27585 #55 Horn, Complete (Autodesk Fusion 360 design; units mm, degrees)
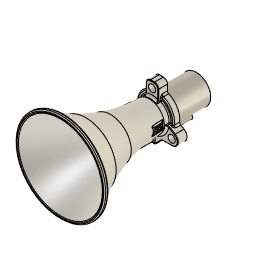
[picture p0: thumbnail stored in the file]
parameter "Bolt_Hole_Tolerance" = 1.5875 (= "( 1 / 16 ) * 1 in")
parameter "Dowel_Hole_Tolerance" = 0.0248 (= "( 1 / 1024 ) * 1 in")
parameter "d277" = 55
parameter "d278" = 1.7223
parameter "d279" = 63
parameter "d280" = 1.5875 (= "( 1 / 16 ) * 1 in")
parameter "d281" = 0.5095
parameter "d282" = 0.5095 (= "d281")
parameter "d283" = 0.5095 (= "d281")
parameter "d284" = 0.5095 (= "d281")
parameter "d285" = 1.5875 (= "( 1 / 16 ) * 1 in")
parameter "d287" = 0.4159
parameter "d288" = 9.219
parameter "d289" = 0.6307
parameter "d290" = 0.4047
parameter "d291" = 0.4047 (= "d290")
parameter "d292" = 0.4571
parameter "d293" = 0.4571 (= "d292")
parameter "d294" = 1.5875 (= "( 1 / 16 ) * 1 in")
parameter "d295" = 1.5875 (= "( 1 / 16 ) * 1 in")
parameter "d296" = 1.5875 (= "( 1 / 16 ) * 1 in")
parameter "d297" = 1.5875 (= "d296")
parameter "d298" = 0.3969 (= "( 1 / 64 ) * 1 in")
parameter "d299" = 0.3969 (= "( 1 / 64 ) * 1 in")
parameter "d300" = 0.3969 (= "( 1 / 64 ) * 1 in")
parameter "d301" = 0.3969 (= "d300")
parameter "d302" = 0.4047 (= "d290")
parameter "d303" = 0.4047 (= "d302")
parameter "d304" = 0.7839 (= "d305")
parameter "d305" = 0.7839
parameter "d306" = 0.7839 (= "d305")
parameter "d307" = 0.3969 (= "( 1 / 64 ) * 1 in")
parameter "d308" = 0.3969 (= "d307")
parameter "d309" = 1.5875 (= "( 1 / 16 ) * 1 in")
parameter "d310" = 0.7937 (= "( 1 / 32 ) * 1 in")
parameter "d311" = 0.3969 (= "( 1 / 64 ) * 1 in")
parameter "d312" = 0.3969 (= "( 1 / 64 ) * 1 in")
parameter "d313" = 1.5875 (= "( 1 / 16 ) * 1 in")
parameter "d314" = 0.3969 (= "( 1 / 64 ) * 1 in")
parameter "d317" = 0.3969 (= "( 1 / 64 ) * 1 in")
parameter "d318" = 109
parameter "d319" = 0.3969 (= "( 1 / 64 ) * 1 in")
parameter "d320" = 1.5875 (= "( 1 / 16 ) * 1 in")
parameter "d321" = 0.3969 (= "( 1 / 64 ) * 1 in")
parameter "d322" = 0.3969 (= "( 1 / 64 ) * 1 in")
parameter "d323" = 109
parameter "d324" = 0.7937 (= "( 1 / 32 ) * 1 in")
parameter "d326" = 0.3969 (= "( 1 / 64 ) * 1 in")
parameter "d327" = 0.3969 (= "( 1 / 64 ) * 1 in")
parameter "d328" = 1.5875 (= "( 1 / 16 ) * 1 in")
parameter "d329" = 1.7223 (= "d278")
parameter "d330" = 0.3969 (= "( 1 / 64 ) * 1 in")
parameter "d331" = 0.3969 (= "d330")
parameter "d332" = 1.3496
parameter "d333" = 0.3969 (= "d330")
parameter "d334" = 1.5875 (= "( 1 / 16 ) * 1 in")
parameter "d335" = 0.3969 (= "d330")
parameter "d342" = 1.5875 (= "( 1 / 16 ) * 1 in")
parameter "d336" = 0.3969 (= "( 1 / 64 ) * 1 in")
parameter "d337" = 0.3969 (= "d336")
parameter "d338" = 0.3969 (= "d337")
parameter "d340" = 0.3969 (= "( 1 / 64 ) * 1 in")
canvas "Canvas1"
sketch "Main Profile" plane through (0, 0, 0) normal (1, 0, 0) x axis (0, 1, 0)
  line L1 (0, -22.225) -> (0, 22.225)
  line L2 (-53.975, 22.225) -> (0, 22.225)
  line L3 (-53.975, 44.45) -> (-53.975, 22.225)
  line L4 (-210.3438, 0) -> (0, 0)
  line L5 (-68.2625, 44.45) -> (-53.975, 44.45)
  line L6 (-53.975, -22.225) -> (0, -22.225)
  line L7 (-53.975, 22.225) -> (-53.975, -22.225)
  line L8 (-53.975, -38.1) -> (-53.975, -22.225)
  line L9 (-68.2625, -38.1) -> (-53.975, -38.1)
  line L10 (-68.2625, 44.45) -> (-68.2625, -38.1)
  line L11 (-67.3186, 16.4106) -> (0, 11.1125)
  line L12 (-63.5, 28.575) -> (-53.975, 28.575)
  line L13 (-63.5, 19.2949) -> (-63.5, 28.575)
  line L14 (-67.0695, 19.5758) -> (-63.5, 19.2949)
  line L15 (-210.3438, -69.0563) -> (-210.3437, 69.0562)
  line L16 (-68.2625, 19.6697) -> (-68.2625, 44.45)
  line L17 (9.1828, 34.925) -> (-68.2625, 34.925)
  line L18 (-34.1313, 22.225) -> (-34.1313, -22.225)
  line L19 (-68.2625, -18.1085) -> (-68.2625, -38.1)
  line L20 (-205.5813, 69.0562) -> (-210.3437, 69.0562)
  line L21 (-205.5812, 65.9557) -> (-205.5813, 69.0562)
  line L22 (-141.1555, -34.925) -> (-68.2625, -34.925)
  line L23 (-67.3186, 0) -> (-67.3186, 16.4106)
  line L24 (-67.3186, -16.4106) -> (0, -11.1125)
  line L25 (-205.5812, -65.9557) -> (-205.5812, -69.0563)
  line L26 (-205.5812, -69.0563) -> (-210.3437, -69.0563)
  line L27 (-67.0695, -19.5758) -> (-63.5, -19.2949)
  line L28 (-63.5, 23.0187) -> (-68.2625, 23.0187)
  line L29 (-72.4156, 23.0187) -> (-68.2625, 23.0187)
  arc A1 centre (-43.4043, 320.271) radius 304.8 clockwise from (-67.3186, 16.4106) to (-210.3438, 65.2529)
  arc A2 centre (-43.4043, 320.271) radius 301.625 clockwise from (-67.0695, 19.5758) to (-210.3438, 69.0562)
  arc A3 centre (-43.4043, -320.271) radius 304.8 clockwise from (-210.3437, -65.2529) to (-67.3186, -16.4106)
  arc A4 centre (-43.4043, -320.271) radius 301.625 clockwise from (-210.3437, -69.0563) to (-67.0695, -19.5758)
  arc A5 centre (-72.4156, 226.2188) radius 203.2 clockwise from (-72.4156, 23.0187) to (-132.3099, 32.0464)
  point P4 (0, 0)
  point P1 (0, 0)
  point P7 (0, 0)
  point P13 (0, 11.1125)
  point P15 (-53.975, 28.575)
  point P21 (-210.3438, 0)
  point P8 (-210.3438, 0)
  point P22 (-68.2625, 19.6697)
  point P23 (-68.2625, 34.925)
  point P25 (-34.1313, -22.225)
  point P26 (-34.1313, 22.225)
  point P27 (-68.2625, -18.1085)
  point P30 (-68.2625, -34.925)
  point P32 (-68.2625, 23.0187)
  point P33 (-210.3438, 65.2529)
  point P37 (-67.3186, 0)
  point P35 (-210.3438, 69.0562)
  point P29 (-205.5812, 65.9557)
  point P19 (-210.3437, 69.0562)
  point P38 (0, -11.1125)
  point P14 (-67.3186, 16.4106)
  point P39 (-67.3186, -16.4106)
  point P17 (-63.5, 19.2949)
  point P48 (-63.5, -19.2949)
  point P18 (-67.0695, 19.5758)
  point P44 (-67.0695, -19.5758)
  point P47 (-210.3437, -69.0563)
  point P28 (-205.5813, 69.0562)
  point P45 (-205.5812, -69.0563)
  point P46 (-205.5812, -65.9557)
  point P41 (-210.3437, -65.2529)
  point P43 (-210.3437, -69.0563)
  point P31 (-141.1555, -34.925)
  point P49 (-63.5, 23.0187)
  point P51 (-132.3099, 32.0464)
  point P2 (0, 22.225)
  point P5 (-53.975, 22.225)
  point P3 (0, -22.225)
  point P6 (-53.975, 44.45)
  point P9 (-68.2625, 44.45)
  point P16 (-63.5, 28.575)
  point P20 (-210.3438, -69.0563)
  point P12 (-68.2625, -38.1)
  vertical L1
  coincident L1 P4
  coincident P1 P4
  midpoint P1 L1
  perpendicular L1 L2
  perpendicular L2 L3
  coincident P1 P7
  perpendicular L1 L4
  perpendicular L3 L5
  perpendicular L1 L6
  vertical L7
  perpendicular L6 L8
  perpendicular L8 L9
  vertical L10
  coincident L1 P13
  coincident L3 P15
  perpendicular L3 L12
  perpendicular L12 L13
  parallel L11 L14
  vertical L15
  midpoint L15 P21
  coincident P8 P21
  coincident L14 P22
  coincident L10 P22
  coincident L10 P23
  perpendicular L16 L17
  coincident L6 P25
  coincident L2 P26
  perpendicular L2 L18
  coincident L10 P27
  perpendicular L9 L19
  perpendicular L15 L20
  vertical L21
  coincident L10 P30
  perpendicular L19 L22
  coincident L10 P32
  coincident L15 P33
  tangent L11 A1
  tangent L14 A2
  concentric A1 A2
  coincident L4 P37
  perpendicular L4 L23
  coincident L15 P35
  coincident P29 A2
  coincident P19 P35
  symmetric L4 P13 P38
  symmetric L4 P14 P39
  symmetric L4 P17 P48
  symmetric L4 P18 P44
  symmetric L4 P19 P47
  symmetric L4 P28 P45
  symmetric L4 P29 P46
  symmetric L4 P33 P41
  symmetric L4 A1 A3
  symmetric L4 P35 P43
  symmetric L4 A2 A4
  coincident P31 A4
  coincident L13 P49
  perpendicular L13 L28
  perpendicular L10 L29
  coincident A2 P51
  tangent L29 A5
  tangent A2 A5
  dimension "d1" distance P2 P5 = 53.975 (= "2 1/8")
  dimension "d2" distance P2 P3 = 44.45 (= "1 3/4")
  dimension "d3" distance P6 L4 = 44.45 (= "1 3/4")
  dimension "d4" distance P6 P9 = 14.2875 (= "( 9 / 16 ) * 1 in")
  dimension "d5" distance L4 L9 = 38.1
  dimension "d6" distance P4 P13 = 11.1125 (= "( 7 / 16 ) * 1 in")
  dimension "d7" distance L11 L14 = 3.175 (= "( 1 / 8 ) * 1 in")
  dimension "d9" distance P15 P16 = 9.525 (= "( 3 / 8 ) * 1 in")
  dimension "d10" distance L4 L12 = 28.575
  dimension "d11" distance L4 L17 = 34.925 (= "1 3/8")
  dimension "d12" distance P19 P20 = 138.1125 (= "5 7/16")
  dimension "d17" distance L1 L18 = 34.1313 (= "1 11/32")
  dimension "d68" distance P19 P28 = 4.7625 (= "( 3 / 16 ) * 1 in")
  dimension "d157" distance L15 L18 = 176.2125 (= "6 15/16")
  dimension "d175" distance P12 P30 = 3.175 (= "( 1 / 8 ) * 1 in")
  dimension "d197" angle L4 L11 = 4.5
  dimension "d216" radius A1 = 304.8
  dimension "d217" distance L12 L28 = 5.5563
  dimension "d218" radius A5 = 203.2
revolve "Revolve1" sketch "Main Profile" AlongAngle 360
revolve "Revolve3" sketch "Main Profile" AlongAngle 360
fillet "Fillet16" radius 158.75
sketch "Flange Profile" plane through (0, -53.975, 0) normal (0, 1, 0) x axis (-1, 0, 0)
  line L1 (0, 34.925) -> (0, 0)
  line L2 (0, 44.45) -> (0, 34.925)
  line L3 (3.175, 44.45) -> (-3.175, 44.45)
  line L4 (9.525, 31.1085) -> (9.525, 38.1)
  line L5 (-30.2459, -17.4625) -> (0, 0)
  line L6 (30.2459, -17.4625) -> (0, 0)
  line L7 (30.2459, -26.9875) -> (15.0812, -26.9875)
  line L8 (29.9633, -6.3008) -> (35.0084, -9.2136)
  line L9 (0, -31.75) -> (0, 0)
  line L10 (0, -38.1) -> (0, -31.75)
  line L11 (3.9688, -38.1) -> (-3.9688, -38.1)
  line L12 (15.0812, -26.9875) -> (3.9688, -38.1)
  line L13 (-15.0812, -26.9875) -> (-3.9688, -38.1)
  line L14 (-30.2459, -26.9875) -> (-15.0812, -26.9875)
  line L15 (-29.9633, -6.3008) -> (-35.0084, -9.2136)
  line L16 (-9.525, 31.1085) -> (-9.525, 38.1)
  line L17 (9.525, 20.0805) -> (9.525, 31.1085)
  line L18 (-9.525, 20.0805) -> (-9.525, 31.1085)
  line L19 (22.1527, -1.7913) -> (29.9633, -6.3008)
  line L20 (-22.1527, -1.7913) -> (-29.9633, -6.3008)
  circle C1 centre (0, 0) radius 22.225
  circle C2 centre (0, 34.925) radius 5.5563
  arc A1 centre (3.175, 38.1) radius 6.35 clockwise from (3.175, 44.45) to (9.525, 38.1)
  arc A2 centre (15.875, 31.1085) radius 6.35 clockwise from (12.9886, 25.4524) to (9.525, 31.1085)
  arc A3 centre (0, 0) radius 28.575 clockwise from (12.9886, 25.4524) to (28.3957, -3.196)
  circle C3 centre (-30.2459, -17.4625) radius 5.5563
  circle C4 centre (30.2459, -17.4625) radius 5.5563
  arc A4 centre (30.2459, -17.4625) radius 9.525 clockwise from (35.0084, -9.2136) to (30.2459, -26.9875)
  arc A5 centre (31.5508, -3.5512) radius 3.175 clockwise from (29.9633, -6.3008) to (28.3957, -3.196)
  circle C5 centre (0, -31.75) radius 3.9688
  arc A6 centre (-30.2459, -17.4625) radius 9.525 clockwise from (-30.2459, -26.9875) to (-35.0084, -9.2136)
  arc A7 centre (-31.5508, -3.5512) radius 3.175 clockwise from (-28.3957, -3.196) to (-29.9633, -6.3008)
  arc A8 centre (0, 0) radius 28.575 clockwise from (-28.3957, -3.196) to (-12.9886, 25.4524)
  arc A9 centre (-15.875, 31.1085) radius 6.35 clockwise from (-9.525, 31.1085) to (-12.9886, 25.4524)
  arc A10 centre (-3.175, 38.1) radius 6.35 clockwise from (-9.525, 38.1) to (-3.175, 44.45)
  circle C6 centre (0, 0) radius 28.575
  point P1 (0, 0)
  point P3 (0, 0)
  point P4 (0, 34.925)
  point P5 (0, 34.925)
  point P6 (0, 34.925)
  point P10 (0, 44.45)
  point P7 (0, 44.45)
  point P30 (0, 0)
  point P31 (0, -31.75)
  point P32 (0, -31.75)
  point P33 (0, -31.75)
  point P37 (0, -38.1)
  point P34 (0, -38.1)
  point P9 (3.175, 44.45)
  point P52 (-3.175, 44.45)
  point P11 (9.525, 38.1)
  point P50 (-9.525, 38.1)
  point P13 (9.525, 31.1085)
  point P49 (-9.525, 31.1085)
  point P14 (12.9886, 25.4524)
  point P47 (-12.9886, 25.4524)
  point P16 (28.3957, -3.196)
  point P45 (-28.3957, -3.196)
  point P24 (15.0812, -26.9875)
  point P39 (-15.0812, -26.9875)
  point P25 (30.2459, -26.9875)
  point P40 (-30.2459, -26.9875)
  point P26 (35.0084, -9.2136)
  point P42 (-35.0084, -9.2136)
  point P28 (29.9633, -6.3008)
  point P43 (-29.9633, -6.3008)
  point P36 (3.9688, -38.1)
  point P38 (-3.9688, -38.1)
  point P53 (9.525, 20.0805)
  point P54 (-9.525, 20.0805)
  point P55 (22.1527, -1.7913)
  point P56 (-22.1527, -1.7913)
  point P35 (-3.9688, -38.1)
  point P19 (0, 0)
  coincident P1 P3
  vertical L1
  coincident P4 P5
  coincident P5 P6
  parallel L1 L2
  horizontal L3
  coincident L3 P10
  midpoint L3 P10
  coincident P7 P10
  tangent L3 A1
  vertical L4
  tangent A1 L4
  tangent L4 A2
  tangent A2 A3
  concentric C1 A3
  horizontal L7
  tangent L7 A4
  concentric C4 A4
  tangent A4 L8
  tangent L8 A5
  tangent A3 A5
  coincident P1 P30
  vertical L9
  coincident P31 P32
  coincident P32 P33
  parallel L9 L10
  horizontal L11
  midpoint L11 P37
  coincident P34 P37
  symmetric L1 P9 P52
  symmetric L1 P11 P50
  symmetric L1 A1 A10
  symmetric L1 P13 P49
  symmetric L1 P14 P47
  symmetric L1 A2 A9
  symmetric L1 P16 P45
  symmetric L1 A3 A8
  symmetric L1 P24 P39
  symmetric L1 P25 P40
  symmetric L1 P26 P42
  symmetric L1 A4 A6
  symmetric L1 P28 P43
  symmetric L1 A5 A7
  symmetric L1 P36 P38
  coincident C1 P53
  tangent A2 L17
  tangent A9 L18
  coincident C1 P54
  coincident C1 P55
  tangent A5 L19
  coincident C1 P56
  tangent A7 L20
  dimension "d95" distance P3 P4 = 34.925 (= "1 3/8")
  dimension "d96" diameter C2 = 11.1125 (= "( 3 / 8 ) * 1 in + Bolt_Hole_Tolerance")
  dimension "d97" radius A1 = 6.35 (= "( 1 / 4 ) * 1 in")
  dimension "d98" distance P1 L3 = 44.45 (= "1 3/4")
  dimension "d99" distance P5 L4 = 9.525 (= "( 3 / 8 ) * 1 in")
  dimension "d100" radius A2 = 6.35 (= "( 1 / 4 ) * 1 in")
  dimension "d101" radius A3 = 28.575 (= "1 1/8")
  dimension "d104" radius A4 = 9.525 (= "( 3 / 8 ) * 1 in")
  dimension "d105" angle L7 L8 = 30
  dimension "d106" radius A5 = 3.175 (= "( 1 / 8 ) * 1 in")
  dimension "d107" distance P30 P31 = 31.75 (= "1 1/4")
  dimension "d108" diameter C5 = 7.9375 (= "( 5 / 16 ) * 1 in")
  dimension "d109" distance P35 P36 = 7.9375 (= "( 5 / 16 ) * 1 in")
  dimension "d110" angle L7 L12 = 135
  dimension "d111" distance P19 L11 = 38.1 (= "1 1/2")
  dimension "d103" C-Pattern1-Angle = 360
extrude "Extrude2" add sketch "Flange Profile" profile of C1 C2 L3 A1 L4 C3 C4 L7 A4 L8 C5 L11 L12 L13 L14 A6 L15 L16 A10 L17 L18 L19 L20 against normal blind 14.2875 (magnitude of "( -9 / 16 ) * 1 in")
extrude "Extrude6" add sketch "Main Profile" profile of L19 L22 along normal blind 3.175 (= "( 1 / 8 ) * 1 in")
mirror "Mirror5" mirrorStitchTolerance 0.1016
delete_face "DeleteFace14"
delete_face "DeleteFace15"
extrude "Extrude4" cut sketch "Flange Profile" profile of C2 C3 C4 against normal blind 14.3002
extrude "Extrude5" cut sketch "Flange Profile" profile of C5 against normal blind 9.525 (magnitude of "( -3 / 8 ) * 1 in")
fillet "Fillet27" radius 3.175 (= "( 1 / 8 ) * 1 in")
fillet "Fillet28" radius 1.5875 (= "( 1 / 16 ) * 1 in")
fillet "Fillet29" radius 25.4
fillet "Fillet30" radius 1.5875 (= "( 1 / 16 ) * 1 in")
fillet "Fillet31" radius 0.7937 (= "( 1 / 32 ) * 1 in")
sketch "Main Profile" plane through (0, -63.5, 0) normal (0, 1, 0) x axis (-1, 0, 0)
  circle C1 centre (0, -31.75) radius 3.9687
  circle C2 centre (0, -31.75) radius 3.175
  concentric C1 C2
  dimension "d137" diameter C2 = 6.35 (= "( 1 / 4 ) * 1 in")
extrude "Extrude1" new body sketch "Main Profile" along normal blind 53.975 (= "2 1/8") bodies "27281 Orifice Pin #5"
offset_faces "OffsetFaces1"
work_plane "WorkPlane1" RotateAngle -180
sketch "Orifice & Number Profile" plane through (0, -43.2509, -35.7188) normal (0, 0, -1) x axis (1, 0, 0)
  line L1 (3.9688, -33.7259) -> (-3.9687, -33.7259)
  line L2 (3.9688, 20.2491) -> (-3.9687, 20.2491)
  line L3 (0, 20.2491) -> (0, -33.7259)
  line L4 (-22.225, -43.2509) -> (22.225, -43.2509)
  line L5 (1.5875, -9.1196) -> (1.5875, -33.7259)
  line L6 (0, -9.1196) -> (1.5875, -9.1196)
  circle C1 centre (0, -9.1196) radius 0.9922
  point P6 (0, -33.7259)
  point P7 (0, 20.2491)
  point P8 (0, -9.1196)
  point P11 (1.5875, -33.7259)
  point P13 (0, -9.1196)
  point P12 (1.5875, -9.1196)
  midpoint L1 P6
  midpoint L2 P7
  coincident L3 P8
  coincident L1 P11
  perpendicular L1 L5
  coincident L3 P13
  perpendicular L3 L6
  coincident P8 P13
  dimension "d143" diameter C1 = 1.9844 (= "( 5 / 64 ) * 1 in")
  dimension "d144" distance P8 L4 = 34.1313
  dimension "d145" distance P12 P13 = 1.5875 (= "( 1 / 16 ) * 1 in")
  dimension "d146" Text1-Height = 3.175 (= "( 1 / 8 ) * 1 in")
emboss "Emboss1" sketch "Orifice & Number Profile" Depth -0.1984 (= "( -1 / 128 ) * 1 in") Horizontal Distance 0 Vertical Distance 0 Rotation Angle 0
extrude "Extrude2" cut sketch "Orifice & Number Profile" profile of C1 against normal blind 3.175 (magnitude of "( -1 / 8 ) * 1 in")
fillet "Fillet32" radius 1.5875 (= "( 1 / 16 ) * 1 in")
canvas "Canvas11"
sketch "Branding Profile 1" plane through (0, 0, 0) normal (0, 0, 1) x axis (1, 0, 0)
  curve K1 (-4.4552, -72.4156) -> (-4.5472, -132.3099)
  line L1 (-32.0464, -132.3099) -> (32.0464, -132.3099)
  curve K2 (4.5472, -132.3099) -> (4.4552, -72.4156)
  line L2 (-23.0187, -72.4156) -> (23.0187, -72.4156)
  line L3 (-23.0187, -33.02) -> (-23.0187, -72.4156)
  line L4 (-27.5308, -114.0588) -> (-25.7561, -114.2595)
  line L5 (-23.2509, -76.2) -> (-27.5308, -114.0588)
  line L6 (-21.4762, -76.4006) -> (-23.2509, -76.2)
  line L7 (-25.7561, -114.2595) -> (-21.4762, -76.4006)
  line L8 (-25.7527, -68.2625) -> (-34.6116, -68.2625)
  line L9 (0, 27.94) -> (0, 0)
  line L10 (21.4679, -76.2889) -> (23.2516, -76.2)
  line L11 (22.1, -88.9731) -> (21.4679, -76.2889)
  line L12 (23.8837, -88.8843) -> (22.1, -88.9731)
  line L13 (23.2516, -76.2) -> (23.8837, -88.8843)
  line L14 (34.6116, -68.2625) -> (25.7527, -68.2625)
  arc A1 centre (-225.9403, -72.4576) radius 202.9215 clockwise from (-23.0187, -72.4156) to (-32.0464, -132.3099)
  arc A2 centre (225.9403, -72.4576) radius 202.9215 clockwise from (32.0464, -132.3099) to (23.0187, -72.4156)
  point P9 (-23.0187, -72.4156)
  point P11 (-23.0187, -72.4156)
  point P5 (-32.0464, -132.3099)
  point P10 (-32.0464, -132.3099)
  point P13 (-23.0187, -72.4156)
  point P19 (-27.3336, -114.0811)
  point P20 (-23.0537, -76.2223)
  point P1 (0, 0)
  point P23 (0, 0)
  point P26 (32.0464, -132.3099)
  point P27 (23.0187, -72.4156)
  point P32 (23.6855, -88.8941)
  point P33 (23.0534, -76.2099)
  point P17 (-23.2509, -76.2)
  point P16 (-27.5308, -114.0588)
  point P15 (-25.7561, -114.2595)
  point P28 (23.2516, -76.2)
  point P31 (23.8837, -88.8843)
  point P29 (21.4679, -76.2889)
  coincident P9 P11
  coincident P5 P10
  coincident P9 P13
  perpendicular L2 L3
  tangent A1 L3
  perpendicular L4 L5
  perpendicular L5 L6
  parallel L5 L7
  coincident L4 P19
  coincident A1 P19
  coincident L6 P20
  coincident A1 P20
  coincident P1 P23
  vertical L9
  symmetric P10 L9 P26
  symmetric P11 L9 P27
  symmetric A1 L9 A2
  perpendicular L10 L11
  perpendicular L11 L12
  perpendicular L12 L13
  coincident A2 P32
  coincident L12 P32
  coincident A2 P33
  coincident L10 P33
  dimension "d219" distance P17 P20 = 0.1984 (= "d220")
  dimension "d220" distance P16 P19 = 0.1984 (= "( 1 / 128 ) * 1 in")
  dimension "d221" distance P16 P17 = 38.1 (= "1 1/2")
  dimension "d222" distance P15 P19 = 1.5875 (= "( 1 / 16 ) * 1 in")
  dimension "d223" distance P17 L8 = 7.9375 (= "( 5 / 16 ) * 1 in")
  dimension "d441" distance P28 P33 = 0.1984 (= "( 1 / 128 ) * 1 in")
  dimension "d442" distance P31 P32 = 0.1984 (= "d441")
  dimension "d443" distance P29 P33 = 1.5875 (= "( 1 / 16 ) * 1 in")
  dimension "d445" distance P28 L14 = 7.9375 (= "( 5 / 16 ) * 1 in")
  dimension "d446" distance P28 P31 = 12.7 (= "( 1 / 2 ) * 1 in")
extrude "Extrude10" add sketch "Branding Profile 1" profile of A1 L4 L5 L6 L7 distance 19.05 (= "( 3 / 4 ) * 1 in")
sketch "Branding Profile 2" plane through (-14.4518, 1.6338, 0) normal (-0.9937, 0.1123, 0) x axis (-0.1123, -0.9937, 0)
  line L1 (97.6451, 3.3576) -> (97.6451, 4.8791)
  line L2 (97.7043, -0.6393) -> (95.1168, 2.9021)
  line L3 (89.8256, -0.9636) -> (90.1702, -0.9636)
  line L4 (96.1978, -1.131) -> (93.8099, 2.1371)
  line L5 (83.7378, -6.301) -> (83.7378, 7.809)
  line L6 (87.8356, -6.3626) -> (87.8356, 6.0597)
  line L7 (97.9944, -5.0326) -> (97.9944, -1.5281)
  line L8 (89.3421, 1.0264) -> (89.3421, -1.4472)
  line L9 (82.1033, -8.3956) -> (82.1033, 8.2084)
  line L10 (90.6537, -0.4801) -> (90.6537, 0.0594)
  line L11 (84.5035, -6.7702) -> (85.572, -6.2258)
  line L12 (86.4597, -6.7697) -> (86.4597, -7.1367)
  line L13 (96.1038, -4.6653) -> (95.1387, -4.6653)
  line L14 (89.3421, -4.4596) -> (89.3421, -1.4472)
  line L15 (94.7546, -4.2813) -> (94.7546, -2.0448)
  line L16 (111.1105, 0.5379) -> (110.583, 0.5379)
  line L17 (112.1686, 9.0165) -> (109.0322, 7.6922)
  line L18 (112.6918, 7.8519) -> (112.6918, 8.6696)
  line L19 (110.4365, 6.6498) -> (112.4617, 7.5049)
  line L20 (110.2064, 0.9145) -> (110.2064, 6.3029)
  line L21 (100.5953, 5.487) -> (99.842, 5.487)
  line L22 (105.6043, 6.42) -> (106.3576, 6.6793)
  line L23 (92.2126, 4.8553) -> (92.2126, 5.2322)
  line L24 (96.3625, 3.8359) -> (96.4557, 3.2617)
  line L25 (83.5359, 8.1969) -> (82.9156, 8.6312)
  line L26 (95.0333, 3.158) -> (95.0333, 3.5592)
  line L27 (97.2505, 5.2738) -> (94.1988, 5.2738)
  line L28 (90.1702, 0.5429) -> (89.8256, 0.5429)
  line L29 (89.3421, 1.0264) -> (89.3421, 3.9726)
  line L30 (95.4173, 4.1584) -> (95.9834, 4.1584)
  line L31 (93.7281, 2.3877) -> (93.7281, 4.8031)
  line L32 (91.8002, 5.7567) -> (88.4771, 6.5641)
  line L33 (110.2064, -5.948) -> (110.2064, -1.3453)
  line L34 (101.3017, -4.2166) -> (103.5941, -4.5044)
  line L35 (110.583, -0.9686) -> (111.1105, -0.9686)
  line L36 (106.3576, -6.7165) -> (105.6043, -6.4572)
  line L37 (90.2118, 4.6563) -> (91.5468, 4.3319)
  line L38 (95.0333, 3.5592) -> (95.0333, 3.7743)
  line L39 (94.378, -1.6682) -> (94.3873, -1.6682)
  line L40 (94.0107, -2.0448) -> (94.0107, -5.0326)
  line L41 (96.4879, -4.2813) -> (96.4879, -2.0198)
  line L42 (92.4421, -5.0959) -> (92.4421, -5.528)
  line L43 (90.1792, -5.0926) -> (91.8224, -4.6273)
  line L44 (94.3873, -5.4092) -> (97.6178, -5.4092)
  line L45 (86.0666, -7.7782) -> (83.3525, -9.1611)
  line L46 (92.0613, -6.0315) -> (88.6683, -6.9922)
  line L47 (112.5657, -7.2726) -> (110.4259, -6.2903)
  line L48 (103.5002, -6.011) -> (100.1248, -5.5871)
  line L49 (106.8569, 6.3232) -> (106.8569, -6.3604)
  line L50 (108.5719, -6.6138) -> (108.5719, 6.9982)
  line L51 (110.2064, 0.9145) -> (110.2064, -1.3453)
  line L52 (100.9719, -3.8429) -> (100.9719, 5.1103)
  line L53 (109.0109, -7.2984) -> (112.2514, -8.7861)
  line L54 (105.3503, -6.1011) -> (105.3503, 6.0639)
  line L55 (99.4654, -4.8397) -> (99.4654, 5.1103)
  line L56 (112.7852, -8.4438) -> (112.7852, -7.6149)
  line L57 (111.4872, -0.592) -> (111.4872, 0.1613)
  line L58 (103.9238, -4.8781) -> (103.9238, -5.6373)
  arc A1 centre (91.9551, -5.0959) radius 0.487 clockwise from (91.8224, -4.6273) to (92.4421, -5.0959)
  arc A2 centre (94.3873, -2.0448) radius 0.3766 clockwise from (94.0107, -2.0448) to (94.3873, -1.6682)
  arc A3 centre (89.8256, -1.4472) radius 0.4835 clockwise from (89.3421, -1.4472) to (89.8256, -0.9636)
  arc A4 centre (90, -4.4596) radius 0.6578 clockwise from (90.1792, -5.0926) to (89.3421, -4.4596)
  arc A5 centre (94.9813, -2.0198) radius 1.5065 clockwise from (96.1978, -1.131) to (96.4879, -2.0198)
  arc A6 centre (94.378, -2.0448) radius 0.3766 clockwise from (94.378, -1.6682) to (94.7546, -2.0448)
  arc A7 centre (95.1387, -4.2813) radius 0.3841 clockwise from (95.1387, -4.6653) to (94.7546, -4.2813)
  arc A8 centre (82.9625, -8.3956) radius 0.8592 clockwise from (83.3525, -9.1611) to (82.1033, -8.3956)
  arc A9 centre (85.7398, -7.1367) radius 0.7199 clockwise from (86.4597, -7.1367) to (86.0666, -7.7782)
  arc A10 centre (85.8492, -6.7697) radius 0.6105 clockwise from (85.572, -6.2258) to (86.4597, -6.7697)
  arc A11 centre (99.842, 5.1103) radius 0.3766 clockwise from (99.4654, 5.1103) to (99.842, 5.487)
  arc A12 centre (106.4802, 6.3232) radius 0.3766 clockwise from (106.3576, 6.6793) to (106.8569, 6.3232)
  arc A13 centre (110.583, 0.9145) radius 0.3766 clockwise from (110.583, 0.5379) to (110.2064, 0.9145)
  arc A14 centre (112.3151, 7.8519) radius 0.3766 clockwise from (112.6918, 7.8519) to (112.4617, 7.5049)
  arc A15 centre (109.3252, 6.9982) radius 0.7533 clockwise from (108.5719, 6.9982) to (109.0322, 7.6922)
  arc A16 centre (100.5953, 5.1103) radius 0.3766 clockwise from (100.5953, 5.487) to (100.9719, 5.1103)
  arc A17 centre (112.3151, 8.6696) radius 0.3766 clockwise from (112.1686, 9.0165) to (112.6918, 8.6696)
  arc A18 centre (105.727, 6.0639) radius 0.3766 clockwise from (105.3503, 6.0639) to (105.6043, 6.42)
  arc A19 centre (111.1105, 0.1613) radius 0.3766 clockwise from (111.1105, 0.5379) to (111.4872, 0.1613)
  arc A20 centre (97.2505, 4.8791) radius 0.3947 clockwise from (97.2505, 5.2738) to (97.6451, 4.8791)
  arc A21 centre (82.6195, 8.2084) radius 0.5162 clockwise from (82.1033, 8.2084) to (82.9156, 8.6312)
  arc A22 centre (95.9834, 3.7743) radius 0.3841 clockwise from (95.9834, 4.1584) to (96.3625, 3.8359)
  arc A23 centre (90.0457, 3.9726) radius 0.7035 clockwise from (89.3421, 3.9726) to (90.2118, 4.6563)
  arc A24 centre (91.674, 4.8553) radius 0.5386 clockwise from (92.2126, 4.8553) to (91.5468, 4.3319)
  arc A25 centre (91.6728, 5.2322) radius 0.5398 clockwise from (91.8002, 5.7567) to (92.2126, 5.2322)
  arc A26 centre (95.4671, 3.158) radius 0.4338 clockwise from (95.1168, 2.9021) to (95.0333, 3.158)
  arc A27 centre (94.1988, 4.8031) radius 0.4706 clockwise from (93.7281, 4.8031) to (94.1988, 5.2738)
  arc A28 centre (89.8256, 1.0264) radius 0.4835 clockwise from (89.8256, 0.5429) to (89.3421, 1.0264)
  arc A29 centre (83.2643, 7.809) radius 0.4736 clockwise from (83.5359, 8.1969) to (83.7378, 7.809)
  arc A30 centre (88.3546, 6.0597) radius 0.519 clockwise from (87.8356, 6.0597) to (88.4771, 6.5641)
  arc A31 centre (90.1702, 0.0594) radius 0.4835 clockwise from (90.1702, 0.5429) to (90.6537, 0.0594)
  arc A32 centre (110.583, 6.3029) radius 0.3766 clockwise from (110.2064, 6.3029) to (110.4365, 6.6498)
  arc A33 centre (106.4802, -6.3604) radius 0.3766 clockwise from (106.8569, -6.3604) to (106.3576, -6.7165)
  arc A34 centre (111.1105, -0.592) radius 0.3766 clockwise from (111.4872, -0.592) to (111.1105, -0.9686)
  arc A35 centre (105.727, -6.1011) radius 0.3766 clockwise from (105.6043, -6.4572) to (105.3503, -6.1011)
  arc A36 centre (101.3486, -3.8429) radius 0.3766 clockwise from (101.3017, -4.2166) to (100.9719, -3.8429)
  arc A37 centre (103.5472, -4.8781) radius 0.3766 clockwise from (103.5941, -4.5044) to (103.9238, -4.8781)
  arc A38 centre (110.583, -1.3453) radius 0.3766 clockwise from (110.2064, -1.3453) to (110.583, -0.9686)
  arc A39 centre (95.4173, 3.7743) radius 0.3841 clockwise from (95.0333, 3.7743) to (95.4173, 4.1584)
  arc A40 centre (94.1529, 2.3877) radius 0.4248 clockwise from (93.8099, 2.1371) to (93.7281, 2.3877)
  arc A41 centre (97.0466, 3.3576) radius 0.5986 clockwise from (97.6451, 3.3576) to (96.4557, 3.2617)
  arc A42 centre (84.2644, -6.301) radius 0.5266 clockwise from (84.5035, -6.7702) to (83.7378, -6.301)
  arc A43 centre (97.6178, -5.0326) radius 0.3766 clockwise from (97.9944, -5.0326) to (97.6178, -5.4092)
  arc A44 centre (94.3873, -5.0326) radius 0.3766 clockwise from (94.3873, -5.4092) to (94.0107, -5.0326)
  arc A45 centre (96.1038, -4.2813) radius 0.3841 clockwise from (96.4879, -4.2813) to (96.1038, -4.6653)
  arc A46 centre (91.9187, -5.528) radius 0.5233 clockwise from (92.4421, -5.528) to (92.0613, -6.0315)
  arc A47 centre (90.1702, -0.4801) radius 0.4835 clockwise from (90.6537, -0.4801) to (90.1702, -0.9636)
  arc A48 centre (88.49, -6.3626) radius 0.6544 clockwise from (88.6683, -6.9922) to (87.8356, -6.3626)
  arc A49 centre (96.4879, -1.5281) radius 1.5065 clockwise from (97.7043, -0.6393) to (97.9944, -1.5281)
  arc A50 centre (109.3252, -6.6138) radius 0.7533 clockwise from (109.0109, -7.2984) to (108.5719, -6.6138)
  arc A51 centre (112.4086, -8.4438) radius 0.3766 clockwise from (112.7852, -8.4438) to (112.2514, -8.7861)
  arc A52 centre (110.583, -5.948) radius 0.3766 clockwise from (110.4259, -6.2903) to (110.2064, -5.948)
  arc A53 centre (103.5472, -5.6373) radius 0.3766 clockwise from (103.9238, -5.6373) to (103.5002, -6.011)
  arc A54 centre (100.2187, -4.8397) radius 0.7533 clockwise from (100.1248, -5.5871) to (99.4654, -4.8397)
  arc A55 centre (112.4086, -7.6149) radius 0.3766 clockwise from (112.5657, -7.2726) to (112.7852, -7.6149)
  point P65 (83.7378, -6.301)
  point P67 (83.7378, -6.301)
  point P148 (100.9719, -3.8429)
  point P164 (100.9719, -3.8429)
  point P27 (111.4872, -0.2154)
  point P11 (108.5719, -6.6138)
  point P31 (108.5719, -6.6138)
  tangent L9 A21
  tangent A21 L25
  tangent L25 A29
  tangent L5 A29
  vertical L5
  tangent L9 A8
  tangent A8 L45
  tangent A9 L45
  vertical L12
  tangent L12 A9
  tangent L12 A10
  tangent L11 A10
  parallel L11 L45
  tangent L11 A42
  coincident P65 P67
  tangent L5 A42
  vertical L6
  tangent L6 A30
  tangent A30 L32
  tangent A25 L32
  tangent L23 A25
  vertical L23
  tangent L23 A24
  tangent A24 L37
  parallel L32 L37
  tangent A23 L37
  vertical L29
  tangent A23 L29
  tangent L29 A28
  tangent L28 A28
  horizontal L28
  tangent L28 A31
  tangent L10 A31
  vertical L10
  tangent L10 A47
  horizontal L3
  tangent L3 A47
  tangent L3 A3
  vertical L14
  tangent A3 L14
  vertical L8
  tangent L6 A48
  tangent L46 A48
  tangent A46 L46
  vertical L42
  tangent L42 A46
  tangent A1 L42
  tangent A1 L43
  tangent A4 L43
  tangent A4 L14
  parallel L43 L46
  horizontal L27
  tangent A20 L27
  vertical L1
  tangent L1 A20
  tangent L1 A41
  tangent L24 A41
  tangent L24 A22
  tangent A22 L30
  horizontal L30
  tangent L30 A39
  vertical L38
  tangent A39 L38
  tangent L27 A27
  vertical L31
  tangent A27 L31
  tangent L31 A40
  tangent L4 A40
  parallel L26 L38
  tangent A26 L26
  tangent L2 A26
  parallel L2 L4
  tangent L2 A49
  vertical L7
  tangent L7 A49
  tangent L4 A5
  tangent A5 L41
  vertical L41
  tangent L7 A43
  horizontal L44
  tangent A43 L44
  tangent A44 L44
  vertical L40
  tangent L40 A44
  tangent A2 L40
  horizontal L39
  tangent A2 L39
  tangent A6 L39
  vertical L15
  tangent A6 L15
  tangent A7 L15
  tangent L41 A45
  tangent A7 L13
  tangent L13 A45
  vertical L55
  tangent A11 L55
  horizontal L21
  tangent A11 L21
  tangent A16 L21
  vertical L52
  tangent A16 L52
  tangent A54 L55
  tangent L48 A54
  tangent L48 A53
  vertical L58
  tangent A53 L58
  tangent A37 L58
  tangent L34 A37
  parallel L34 L48
  tangent L34 A36
  coincident P148 P164
  tangent A36 L52
  vertical L54
  tangent A35 L54
  tangent A35 L36
  tangent A33 L36
  vertical L49
  tangent A33 L49
  tangent A12 L49
  tangent A12 L22
  tangent A18 L22
  tangent A18 L54
  tangent A15 L50
  tangent L17 A15
  tangent L17 A17
  tangent L18 A17
  vertical L18
  tangent A14 L18
  tangent A14 L19
  parallel L17 L19
  tangent L19 A32
  vertical L20
  tangent L20 A32
  tangent A13 L20
  horizontal L16
  tangent L16 A13
  tangent L16 A19
  vertical L57
  tangent A19 L57
  tangent A34 L57
  horizontal L35
  tangent A34 L35
  tangent L35 A38
  vertical L33
  tangent L33 A38
  vertical L51
  midpoint P27 L57
  tangent L33 A52
  tangent L47 A52
  tangent L47 A55
  vertical L56
  tangent L56 A55
  tangent A51 L56
  tangent A51 L53
  parallel L47 L53
  tangent A50 L53
  coincident P11 P31
  tangent A50 L50
  dimension "d357" angle L9 L25 = 55
  dimension "d359" angle L9 L45 = 63
  dimension "d367" angle L1 L24 = 9.219
  dimension "d371" radius A40 = 0.4248
  dimension "d384" distance L27 L30 = 1.1154
  dimension "d395" angle L36 L54 = 109
  dimension "d400" angle L22 L54 = 109
  dimension "d339" angle L47 L56 = 114.659
extrude "Extrude12" add sketch "Branding Profile 2" profile of L1 L2 L3 A1 A2 A3 L4 L5 A4 L6 L7 L9 A5 L10 A6 L11 A7 L12 A8 L13 L14 L15 A9 A10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 along normal blind 0.3969 (= "( 1 / 64 ) * 1 in") taper -30
delete_face "DeleteFace16"
work_plane "WorkPlane1" AlongDistance 114.3
fillet "Fillet41" radius 6.35 (= "( 1 / 4 ) * 1 in")
fillet "Fillet42" radius 3.175 (= "( 1 / 8 ) * 1 in")
fillet "Fillet43" radius 0.7937 (= "( 1 / 32 ) * 1 in")
extrude "Extrude14" add sketch "Branding Profile 1" profile of A2 L10 L11 L12 L13 distance 9.525 (= "( 3 / 8 ) * 1 in")
fillet "Fillet44" radius 6.35 (= "( 1 / 4 ) * 1 in")
fillet "Fillet45" radius 3.175 (= "( 1 / 8 ) * 1 in")
fillet "Fillet46" radius 0.7937 (= "( 1 / 32 ) * 1 in")
sketch "Branding Profile 3" plane through (19.4063, 0.967, 0) normal (0.9988, 0.0498, 0) x axis (-0.0498, 0.9988, 0)
  curve K1 (-77.8105, -4.7625) -> (-77.2628, -4.3226)
  line L1 (-77.2628, 4.3226) -> (-77.2628, -4.3226)
  curve K2 (-77.2628, 4.3226) -> (-77.8105, 4.7625)
  line L2 (-89.4236, 4.7625) -> (-77.8105, 4.7625)
  curve K3 (-89.4236, 4.7625) -> (-89.9628, 4.3284)
  line L3 (-89.9628, -4.3284) -> (-89.9628, 4.3284)
  curve K4 (-89.9628, -4.3284) -> (-89.4236, -4.7625)
  line L4 (-77.8105, -4.7625) -> (-89.4236, -4.7625)
  line L5 (-77.2628, 0) -> (-89.9628, 0)
  line L6 (-77.2628, -3.175) -> (-89.9628, -3.175)
  point P10 (-89.9628, 0)
  point P11 (-77.2628, 0)
  point P12 (-89.9628, -3.175)
  point P13 (-77.2628, -3.175)
  midpoint L3 P10
  midpoint L1 P11
  coincident L3 P12
  perpendicular L3 L6
  coincident L1 P13
  dimension "d455" distance L5 L6 = 3.175 (= "( 1 / 8 ) * 1 in")
  dimension "d456" Text1-Height = 9.525 (= "( 3 / 8 ) * 1 in")
extrude "Extrude15" add sketch "Branding Profile 3" along normal blind 0.3969 (= "( 1 / 64 ) * 1 in") taper -25
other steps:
create_component "CreateComponent1"
create_component "CreateComponent2"
named bodies: "27281 Orifice Pin #5", "27467 #55 Horn"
